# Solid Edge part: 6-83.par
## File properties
Author: Ashutosh-CADCIM
Template: iso metric part.par
Last saved by: Ashutosh-CADCIM
Revision: 1
Application: Solid Edge
Accuracy: 0.990
Username: Ashutosh-CADCIM
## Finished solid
Body 1: solid body, 130 faces, 312 edges, 208 vertices.
  Faces by surface: plane 126, cylinder 4
  Edges by curve: line 304, circle 8
Bounding box of the edges (mm): 175.000 x 20.000 x 100.000, from (-87.5, 0, -50) to (87.5, 20, 50).
Cylindrical faces by radius (mm): R20 x4
Planar faces by outward normal: +x 25, +y 25, +z 25, -x 25, -y 1, -z 25
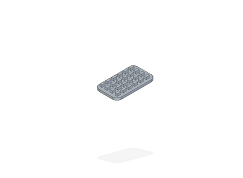
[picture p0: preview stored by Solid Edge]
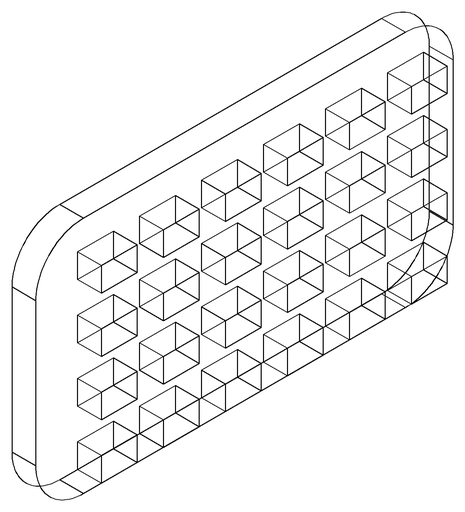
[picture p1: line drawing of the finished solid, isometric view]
